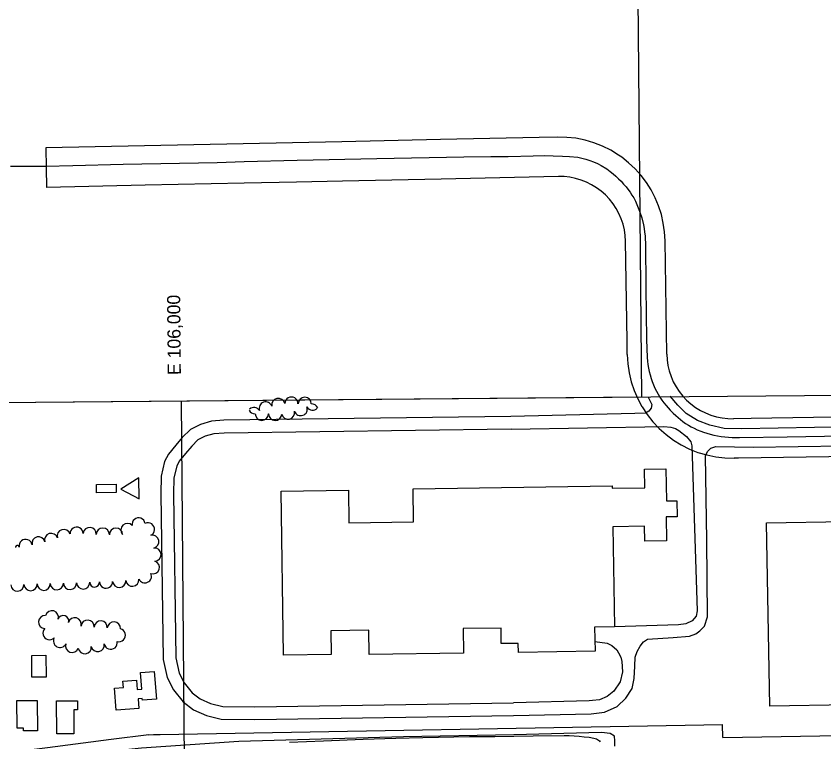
# Model space of a CAD drawing. Extents: x -2233 to 187241, y 4582 to 150524.
# Drawn here: x 105740 to 106969, y 59491 to 60594 of the extents above; entities that cross this region are included whole.
import ezdxf

# ---------------------------------------------------------------- set-up
doc = ezdxf.new("R2010")
doc.units = 0
for name, color, linetype in [('BLDG', 7, 'Continuous'), ('GE_X_CL_2000', 7, 'Continuous'), ('GRID', 7, 'Continuous'), ('ROAD', 7, 'Continuous'), ('RW_X_Fee_RW', 7, 'Continuous'), ('TI_BORDER', 7, 'Continuous'), ('TRANSPWRLN', 7, 'Continuous'), ('TREES', 7, 'Continuous')]:
    doc.layers.add(name, color=color, linetype=linetype)

msp = doc.modelspace()

# ---------------------------------------------------------------- linework, layer by layer
at = {"layer": 'BLDG'}
for points in [[(106245.6, 59873.3), (106246.4, 59823.6), (106344.7, 59825), (106344, 59875.6), (106646.8, 59880), (106646.9, 59876.3), (106696.3, 59877.1), (106695.8, 59905.5), (106728.5, 59906), (106729.2, 59857.2), (106745.2, 59857.4), (106745.6, 59832.9), (106729, 59832.7), (106729.5, 59796.1), (106696.4, 59795.7), (106696.1, 59818.4), (106647.9, 59817.7), (106650.2, 59665.3), (106620.1, 59664.9), (106620.7, 59628.4), (106504.1, 59626.6), (106503.9, 59640.3), (106478, 59639.9), (106477.7, 59663.6), (106420.1, 59662.7), (106420.6, 59625.6), (106277.1, 59623.4), (106276.5, 59660.3), (106218.8, 59659.4), (106219.3, 59623.6), (106146.9, 59622.5), (106143.2, 59871.7)], [(105892.5, 59869.9), (105862.7, 59869.5), (105862.5, 59882.1), (105892.4, 59882.5)], [(107001.4, 59825.9), (107006.4, 59546.8), (106886.4, 59544.7), (106881.3, 59823.7)], [(105764.3, 59588.9), (105764, 59622.1), (105785.6, 59622.2), (105785.9, 59589.1)], [(105932.3, 59554), (105932.1, 59556.6), (105926, 59556.1), (105927.2, 59541.3), (105892.5, 59538.6), (105889.9, 59572.2), (105903.5, 59573.2), (105902.8, 59583), (105923.5, 59584.6), (105924.6, 59570.4), (105931.5, 59570.9), (105929.6, 59596), (105950.3, 59597.6), (105953.6, 59555.6)], [(105751.4, 59507.2), (105751.4, 59511.5), (105741.9, 59511.5), (105741.5, 59553.2), (105772.6, 59553.5), (105773, 59507.4)], [(105833.7, 59553), (105833.9, 59539.3), (105827.9, 59539.3), (105828.2, 59502.7), (105802.4, 59502.5), (105802, 59552.7)]]:
    msp.add_lwpolyline(points, close=True, dxfattribs=at)
at = {"layer": 'GE_X_CL_2000'}
for points in [[(105731.6, 60366.1), (105785.5, 60366.2), (105826.6, 60367.3), (105903.1, 60369.3), (106045.9, 60372), (106087.3, 60373.1), (106167.8, 60375.4), (106288.9, 60378), (106421.4, 60380.2), (106462.3, 60380.7), (106488.7, 60381.1), (106526.6, 60381.9), (106544.2, 60382.4), (106556.8, 60382.2), (106571.4, 60381.7), (106581.9, 60381.1), (106594.4, 60380), (106600.5, 60378.5), (106606.6, 60376.8), (106612.6, 60374.8), (106618.4, 60372.6), (106624.2, 60370.1), (106629.9, 60367.4), (106638.4, 60362), (106643.8, 60358.1), (106648.2, 60354.6), (106652.5, 60351), (106656.5, 60347.2), (106660.5, 60343.2), (106664.2, 60339.1), (106667.9, 60334.8), (106670.4, 60331.5), (106674, 60326.6), (106676.8, 60322.3), (106679.5, 60317.9), (106682, 60313), (106684.3, 60308.1), (106686.5, 60303), (106688.4, 60297.9), (106691.8, 60287.5), (106694.3, 60276.8), (106695.3, 60271.4), (106696.1, 60266), (106696.7, 60260.5), (106697.1, 60255.1), (106697.3, 60249.6), (106697.8, 60181.7), (106698.9, 60102.8), (106699.9, 60075), (106700.4, 60069.7), (106701.1, 60064.3), (106702, 60059.1), (106703.1, 60053.8), (106704.4, 60048.7), (106705.9, 60043.5), (106707.7, 60038.5), (106709.6, 60033.5), (106711.8, 60028.6), (106714.1, 60023.9), (106719.4, 60014.8), (106722.3, 60010.5), (106725.4, 60006.2), (106728.7, 60002.1), (106735, 59995), (106739.4, 59990.6), (106743.3, 59987.1), (106754.2, 59977.8), (106758.4, 59974.9), (106762.7, 59972.3), (106767.1, 59969.8), (106771.6, 59967.5), (106776.2, 59965.3), (106781.8, 59963), (106785.6, 59961.7), (106795.8, 59958.5), (106801.3, 59957.1), (106806.8, 59955.9), (106812.4, 59955), (106818, 59954.3), (106823.6, 59953.8), (106829.3, 59953.5), (106834.9, 59953.5), (106840.6, 59953.7), (106912.8, 59954.7), (106997.9, 59956.2)], [(106156.1, 59489.9), (106207.7, 59491.9), (106268.3, 59494.6), (106318, 59496.2), (106358.8, 59497.1), (106429.6, 59498.6), (106468.2, 59498.5), (106526.6, 59499.8), (106573.7, 59500.4), (106581.3, 59500.2), (106588.9, 59499.9), (106596.5, 59499.3), (106604.1, 59498.4), (106611.6, 59497.4), (106619.1, 59496.1), (106620.9, 59495.7), (106622.7, 59495), (106624.3, 59494.1), (106625.9, 59493.1), (106627.3, 59491.9), (106628.5, 59490.5)]]:
    msp.add_lwpolyline(points, dxfattribs=at)
at = {"layer": 'GRID'}
for p, q in [((109991.1, 60043.6), (104991.3, 60000)), ((105991.2, 60008.7), (106014.8, 57311))]:
    msp.add_line(p, q, dxfattribs=at)
at = {"layer": 'ROAD'}
for p, q in [((106630.3, 59504.5), (106497.1, 59501.1)), ((106634.9, 59504.3), (106630.3, 59504.5)), ((106639, 59503.7), (106634.9, 59504.3)), ((106643.6, 59503.1), (106639, 59503.7)), ((106650.1, 59499.1), (106643.6, 59503.1)), ((106650.9, 59492), (106650.1, 59499.1)), ((106650.9, 59483.9), (106650.9, 59492))]:
    msp.add_line(p, q, dxfattribs=at)
for points in [[(106701.6, 60014.9), (106707.1, 60003.9), (106706, 59997.9), (106702.5, 59993.5), (106697.4, 59990.7), (106681.4, 59989.9), (106492.7, 59985.6)], [(107423.3, 60021.2), (107423.7, 59998.1), (107417.7, 59984.8), (107408, 59977.2), (107393.8, 59974.9), (107009.6, 59969.9), (106843.9, 59966.6), (106816.9, 59967.1), (106795.2, 59972.3), (106776.4, 59979.6), (106759.5, 59990), (106746.6, 60002.6), (106734.7, 60016.4)], [(106492.7, 59985.6), (106056, 59979.7), (106037.5, 59978.4), (106020.8, 59973.5), (106005.3, 59965.6), (105993.1, 59953.6), (105983.1, 59941.6), (105972, 59928.2), (105966.2, 59916.9), (105960.7, 59894.5), (105960.2, 59868), (105963.9, 59616), (105970.2, 59588.2), (105979.7, 59569.6), (105994.5, 59551.3), (106009.9, 59539.2), (106029.8, 59530.4), (106052.3, 59525.2), (106103.6, 59524.5), (106496.9, 59530.5)], [(106492.9, 59966.2), (106056.8, 59960.3), (106040.9, 59959.2), (106027.9, 59955.5), (106016.7, 59949.8), (106007.4, 59940.5), (105998, 59929.3), (105988.3, 59917.5), (105984.5, 59910.1), (105980, 59892), (105979.6, 59868), (105983.2, 59618.3), (105988.5, 59594.9), (105996, 59580.2), (106008.1, 59565.2), (106020, 59555.9), (106035.9, 59548.8), (106054.6, 59544.5), (106103.6, 59543.9), (106496.7, 59549.9)], [(106492.9, 59966.2), (106725.3, 59970.1), (106736.1, 59969), (106743, 59967), (106748.1, 59964.1), (106759.8, 59954.9), (106766.3, 59946.8), (106768.1, 59940.9), (106776.2, 59689.9), (106774.3, 59681.7), (106768.2, 59674.7), (106758.8, 59670.1), (106747.4, 59668.7), (106650.2, 59665.3)], [(106496.9, 59530.5), (106615, 59533), (106635.3, 59535.9), (106654.5, 59544.4), (106667.7, 59556.9), (106677.3, 59571.8), (106680.2, 59586.8), (106681.3, 59605.9), (106681.9, 59619.3), (106684.8, 59627.8), (106689.1, 59636.2), (106694.3, 59642.9), (106700.7, 59646.9), (106739.5, 59649.4), (106764.3, 59651.1), (106774, 59655), (106780, 59659.6), (106787.1, 59666.6), (106791.8, 59680.9), (106790.6, 59797.2), (106788.9, 59925.5), (106791.5, 59932), (106796.9, 59937.2), (106804.3, 59939.9), (106861, 59938.8), (107340.1, 59945.7)], [(106620.4, 59643.2), (106639.1, 59640.4), (106646.2, 59636.9), (106653.8, 59630.4), (106656.6, 59626), (106659.7, 59619.4), (106661.5, 59612.9), (106662.3, 59597.2), (106659, 59581.8), (106649.3, 59567.5), (106639.3, 59559.7), (106627.3, 59554.5), (106616.8, 59553.2), (106611.8, 59553), (106496.7, 59549.9)], [(106497.1, 59501.1), (106329.2, 59498.2), (106079.1, 59491.2), (105930.8, 59481), (105824.7, 59470), (105720.4, 59458.7), (105603.2, 59458), (105486, 59457.6)]]:
    msp.add_lwpolyline(points, dxfattribs=at)
at = {"layer": 'RW_X_Fee_RW'}
for p, q in [((105935.6, 60397.1), (105785.6, 60393.9)), ((105936.5, 60337.1), (105786.5, 60333.9)), ((106729.7, 60080.5), (106727.2, 60252.8)), ((106838.6, 59922.1), (106832, 59922)), ((105959.2, 59501.6), (106814.5, 59517)), ((106814.8, 59497.1), (106814.5, 59517)), ((105942.1, 59501.3), (105949.2, 59501.5)), ((105949.2, 59501.5), (105959.2, 59501.6)), ((106814.8, 59497.1), (106844.8, 59497.6))]:
    msp.add_line(p, q, dxfattribs=at)
for points in [[(106563.8, 60410.4), (106535.5, 60409.8), (106385.5, 60406.7), (106235.5, 60403.5), (106085.6, 60400.3), (105935.6, 60397.1)], [(106661.3, 60379.9), (106656.5, 60383.2), (106644.5, 60390.5), (106632, 60396.8), (106618.9, 60401.9), (106605.5, 60405.8), (106591.7, 60408.6), (106577.8, 60410.1), (106563.8, 60410.4)], [(105785.6, 60393.9), (105786, 60363.9), (105786.5, 60333.9)], [(106727.2, 60252.8), (106726.4, 60266.3), (106724.5, 60279.7), (106721.5, 60292.8), (106717.4, 60305.7), (106712.2, 60318.1), (106706, 60330.1), (106698.8, 60341.5), (106690.6, 60352.3), (106681.6, 60362.3), (106671.8, 60371.5), (106661.3, 60379.9)], [(106565.1, 60350.5), (106386.8, 60346.7), (106236.8, 60343.5), (106166.8, 60342), (106086.9, 60340.3), (105936.5, 60337.1)], [(106667.2, 60252), (106666.7, 60260.7), (106665.4, 60269.4), (106663.3, 60277.9), (106660.6, 60286.2), (106657.1, 60294.2), (106652.9, 60301.9), (106648.1, 60309.2), (106642.6, 60316.1), (106636.6, 60322.5), (106630, 60328.3), (106623, 60333.5), (106615.5, 60338), (106607.7, 60341.9), (106599.5, 60345.1), (106591.1, 60347.6), (106582.5, 60349.3), (106573.8, 60350.3), (106565.1, 60350.5)], [(106669.7, 60079.6), (106669.4, 60100.5), (106667.2, 60252)], [(106669.7, 60079.6), (106670.5, 60065.7), (106672.5, 60051.9), (106675.8, 60038.3), (106680.1, 60025.1), (106685.7, 60012.3), (106691.8, 60000.9), (106692.3, 60000), (106700, 59988.3), (106708.6, 59977.4), (106718.2, 59967.2), (106728.6, 59957.9), (106739.8, 59949.6), (106751.7, 59942.3), (106764.2, 59936), (106777.2, 59930.9), (106790.5, 59926.9), (106804.2, 59924), (106818.1, 59922.4), (106832, 59922)], [(106729.7, 60080.5), (106730.2, 60071.8), (106731.5, 60063.2), (106733.5, 60054.7), (106736.2, 60046.4), (106739.7, 60038.4), (106743.8, 60030.7), (106748.6, 60023.4), (106754, 60016.6), (106760, 60010.3), (106766.5, 60004.5), (106773.5, 59999.3), (106781, 59994.7), (106788.8, 59990.8), (106796.9, 59987.5), (106805.2, 59985), (106813.8, 59983.3), (106822.4, 59982.3), (106831.2, 59982)], [(107269.5, 59988.4), (106953.1, 59983.8), (106858.1, 59982.4), (106831.2, 59982)], [(107270.4, 59928.5), (107044.5, 59925.1), (106838.6, 59922.1)], [(105942.1, 59501.3), (105884.7, 59494), (105788, 59481.5), (105739.7, 59475.3), (105690.1, 59469), (105630.2, 59461.3), (105579.9, 59454.8)], [(106844.8, 59497.6), (107050.7, 59501.3), (107276.5, 59505.4)]]:
    msp.add_lwpolyline(points, dxfattribs=at)
at = {"layer": 'TI_BORDER'}
for p, q in [((106664.5, 63077), (106691.2, 60014.8)), ((106691.2, 60014.8), (99991.5, 59956.3))]:
    msp.add_line(p, q, dxfattribs=at)
at = {"layer": 'TRANSPWRLN'}
msp.add_lwpolyline([(105899.8, 59874.8), (105927.3, 59860.1), (105927, 59892)], close=True, dxfattribs=at)
at = {"layer": 'TREES'}
for centre, radius, start, end in [((106139.1, 60003.1), 10, 12.0605, 192.0605), ((106158.9, 60005), 10, 359.3347, 179.3347), ((106179.2, 60004.8), 10, 359.1448, 179.1448), ((106101.9, 59989.1), 10, 31.7163, 129.9753), ((106119.9, 59997.7), 10, 19.4194, 199.4194), ((106173.2, 59996.7), 10, 199.4194, 19.4194), ((106169, 60004.9), 0.146, 359.1448, 179.1447), ((106191.1, 60005.2), 10, 211.7163, 316.2036), ((106189.8, 59994.6), 10, 22.9406, 93.5311), ((106103.3, 59999.7), 10, 208.3489, 273.5311), ((106113.9, 59989.6), 10, 179.1448, 359.1448), ((106124, 59989.4), 0.146, 179.1448, 359.1447), ((106134.2, 59989.3), 10, 179.3347, 359.3347), ((106154, 59991.3), 10, 192.0605, 12.0605), ((105926.7, 59821.2), 10, 9.2701, 189.2701), ((105832.3, 59807.2), 10, 2.4292, 182.4292), ((105852.3, 59806.7), 10, 355.0939, 175.0939), ((105872.2, 59805.8), 10, 359.4116, 179.4116), ((105892.2, 59805.8), 10, 0.7306, 180.7306), ((105909.5, 59812.8), 10, 43.2352, 223.2352), ((105940.8, 59813.8), 10, 295.2514, 115.2514), ((105774.4, 59792.5), 10, 13.0283, 193.0283), ((105793.7, 59797.7), 10, 17.4562, 197.4562), ((105812.8, 59803.7), 10, 17.4562, 197.4562), ((105947.5, 59795), 10, 283.8145, 103.8145), ((105754.8, 59788.5), 10, 9.7418, 189.7418), ((105742.1, 59786.4), 2.87, 9.7418, 189.7418), ((105950.7, 59775.4), 10, 274.7959, 94.7959), ((105948.3, 59755.9), 10, 251.4845, 71.4845), ((105936.1, 59742.3), 10, 204.5602, 24.5602), ((105742.3, 59729.7), 10, 181.8442, 1.8442), ((105762.3, 59730.4), 10, 181.8442, 1.8442), ((105782.3, 59731), 10, 181.8442, 1.8442), ((105802.3, 59731.7), 10, 181.8442, 1.8442), ((105822.2, 59732.3), 10, 181.8442, 1.8442), ((105842.2, 59732.9), 10, 181.8442, 1.8442), ((105859.7, 59733.5), 7.46, 181.8442, 1.8442), ((105877.1, 59734.2), 10, 182.3929, 2.3929), ((105897.1, 59735.3), 10, 184.3708, 4.3708), ((105917, 59737.1), 10, 185.8188, 5.8188), ((105784.5, 59672.8), 10, 86.5773, 266.5773), ((105794.7, 59680), 10, 343.8651, 163.8651), ((105812.1, 59674.6), 8.19, 341.3919, 161.3919), ((105829.5, 59669.3), 10, 344.3664, 164.3664), ((105849.1, 59665.9), 10, 356.0484, 176.0483), ((105869, 59664.5), 10, 356.1143, 176.1143), ((105889, 59663.2), 10, 356.1143, 176.1143), ((105791, 59655.8), 10, 135.3609, 315.3609), ((105896.5, 59652.8), 10, 255.6178, 75.6178), ((105807, 59644.1), 10, 152.1866, 332.1866), ((105884.2, 59641.3), 10, 190.6547, 10.6547), ((105825.3, 59636.3), 10, 161.9013, 341.9013), ((105844.8, 59634.4), 10, 187.2333, 7.2333), ((105864.5, 59637.6), 10, 190.692, 10.692)]:
    msp.add_arc(centre, radius, start, end, dxfattribs=at)

# ---------------------------------------------------------------- texts
at = {"layer": 'GRID'}
msp.add_text('E 106,000', height=20, rotation=90.5, dxfattribs=at).set_placement((105990.9, 60048.7))

doc.saveas('drawing.dxf')
